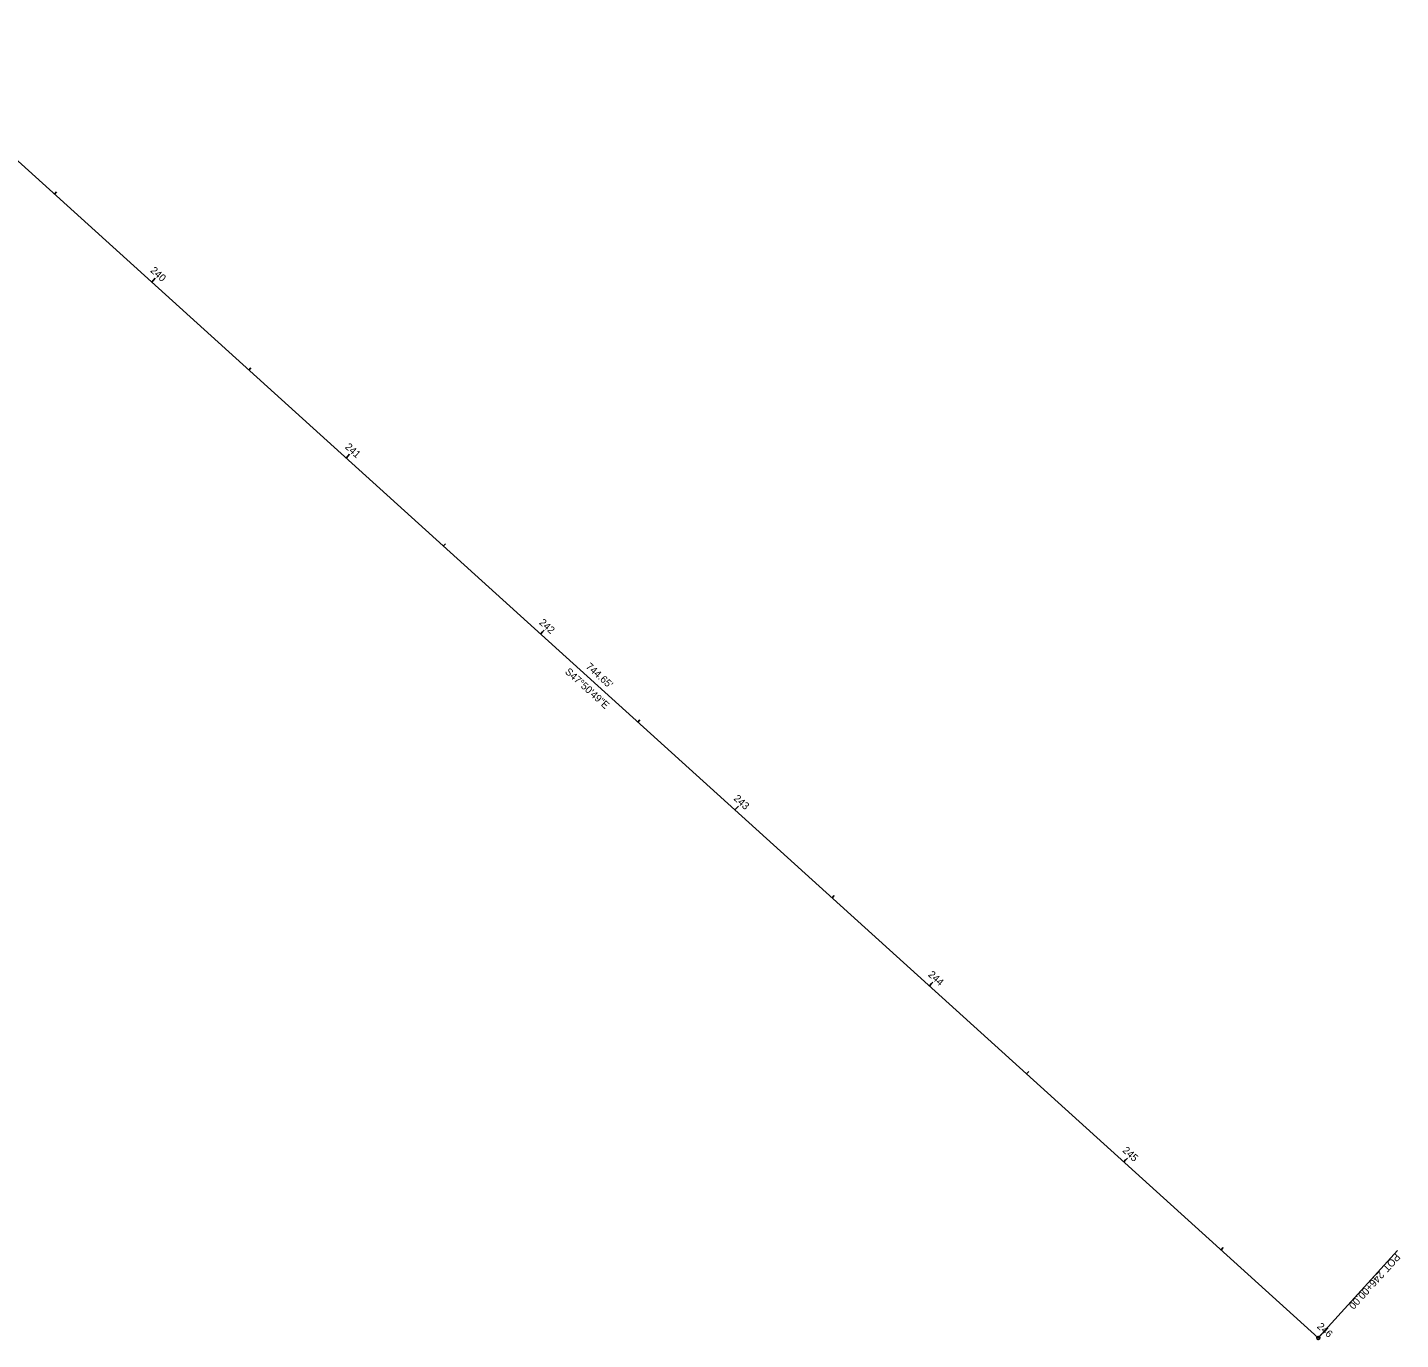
# Model space of a CAD drawing. Extents: x 1471653 to 1473622, y 385397 to 387214.
# Drawn here: x 1473098 to 1473622, y 385397 to 385898 of the extents above; entities that cross this region are included whole.
import ezdxf

# ---------------------------------------------------------------- set-up
doc = ezdxf.new("R2010")
doc.units = 0
for name, color, linetype in [('Default', 7, 'Continuous'), ('DT_P_Graded_Shoulder', 7, 'Continuous'), ('GE_X_Alignment', 7, 'Continuous'), ('PV_P_Curb', 7, 'Continuous'), ('PV_P_EOP', 7, 'Continuous')]:
    doc.layers.add(name, color=color, linetype=linetype)

msp = doc.modelspace()

# ---------------------------------------------------------------- linework, layer by layer
at = {"layer": 'Default'}
for centre in [(1473145.82, 385800.54), (1473145.82, 385800.54), (1473145.82, 385800.54), (1473219.95, 385733.43), (1473294.09, 385666.32), (1473314.61, 385647.75), (1473314.61, 385647.75), (1473314.61, 385647.75), (1473314.61, 385647.75), (1473314.61, 385647.75), (1473314.61, 385647.75), (1473368.23, 385599.21), (1473442.36, 385532.1), (1473516.5, 385464.99), (1473516.5, 385464.99), (1473590.63, 385397.87), (1473590.63, 385397.87), (1473590.63, 385397.87), (1473590.63, 385397.87)]:
    msp.add_circle(centre, 0.0000833, dxfattribs=at)
at = {"layer": 'DT_P_Graded_Shoulder'}
for p, q in [((1473145.82, 385800.54), (1473147.16, 385802.02)), ((1473219.95, 385733.43), (1473220.76, 385734.32)), ((1473294.09, 385666.32), (1473294.89, 385667.21)), ((1473368.23, 385599.21), (1473369.03, 385600.1)), ((1473442.36, 385532.1), (1473443.17, 385532.99)), ((1473516.5, 385464.99), (1473517.84, 385466.47)), ((1473590.63, 385397.87), (1473620.83, 385431.23)), ((1473590.63, 385397.87), (1473591.44, 385398.76))]:
    msp.add_line(p, q, dxfattribs=at)
msp.add_circle((1473590.63, 385397.87), 0.6, dxfattribs=at)
at = {"layer": 'GE_X_Alignment'}
for p, q in [((1473145.82, 385800.54), (1473147.16, 385802.02)), ((1473516.5, 385464.99), (1473517.3, 385465.87)), ((1473590.63, 385397.87), (1473620.83, 385431.23))]:
    msp.add_line(p, q, dxfattribs=at)
msp.add_circle((1473590.63, 385397.87), 0.6, dxfattribs=at)
at = {"layer": 'PV_P_Curb'}
msp.add_line((1473038.58, 385897.62), (1473590.63, 385397.87), dxfattribs=at)
at = {"layer": 'PV_P_EOP'}
for p, q in [((1473108.75, 385834.1), (1473109.56, 385834.99)), ((1473145.82, 385800.54), (1473147.16, 385802.02)), ((1473182.89, 385766.99), (1473183.69, 385767.88)), ((1473219.95, 385733.43), (1473221.3, 385734.91)), ((1473257.02, 385699.87), (1473257.83, 385700.76)), ((1473294.09, 385666.32), (1473295.43, 385667.8)), ((1473331.16, 385632.76), (1473331.96, 385633.65)), ((1473368.23, 385599.21), (1473369.57, 385600.69)), ((1473405.29, 385565.65), (1473406.1, 385566.54)), ((1473442.36, 385532.1), (1473443.7, 385533.58)), ((1473479.43, 385498.54), (1473480.23, 385499.43)), ((1473516.5, 385464.99), (1473517.84, 385466.47)), ((1473553.56, 385431.43), (1473554.37, 385432.32)), ((1473590.63, 385397.87), (1473620.83, 385431.23)), ((1473590.63, 385397.87), (1473591.97, 385399.36))]:
    msp.add_line(p, q, dxfattribs=at)
msp.add_circle((1473590.63, 385397.87), 0.6, dxfattribs=at)

# ---------------------------------------------------------------- texts
at = {"layer": 'DT_P_Graded_Shoulder'}
for s, rotation, p in [('240', 317.847, (1473145.1, 385804.63)), ('S47°50\'49"E', 317.847, (1473303.18, 385651.62)), ("744.65'", 317.847, (1473311.14, 385653.58)), ('245', 317.847, (1473515.76, 385469.08)), ('POT', 227.847, (1473620.11, 385430.37)), ('246+00.00', 227.847, (1473613.99, 385423.6))]:
    msp.add_text(s, height=2.8, rotation=rotation, dxfattribs=at).set_placement(p)
at = {"layer": 'GE_X_Alignment'}
for s, rotation, p in [('240', 317.847, (1473145.1, 385804.63)), ('S47°50\'49"E', 317.847, (1473303.18, 385651.62)), ("744.65'", 317.847, (1473311.14, 385653.58)), ('POT', 227.847, (1473620.11, 385430.37)), ('246+00.00', 227.847, (1473613.99, 385423.6))]:
    msp.add_text(s, height=2.8, rotation=rotation, dxfattribs=at).set_placement(p)
at = {"layer": 'PV_P_EOP'}
for s, rotation, p in [('240', 317.847, (1473145.1, 385804.63)), ('241', 317.847, (1473219.32, 385737.37)), ('242', 317.847, (1473293.34, 385670.37)), ('S47°50\'49"E', 317.847, (1473303.18, 385651.62)), ("744.65'", 317.847, (1473311.14, 385653.58)), ('243', 317.847, (1473367.51, 385603.29)), ('244', 317.847, (1473441.64, 385536.12)), ('245', 317.847, (1473515.76, 385469.08)), ('POT', 227.847, (1473620.11, 385430.37)), ('246+00.00', 227.847, (1473613.99, 385423.6)), ('246', 317.847, (1473589.91, 385401.97))]:
    msp.add_text(s, height=2.8, rotation=rotation, dxfattribs=at).set_placement(p)

doc.saveas('drawing.dxf')
